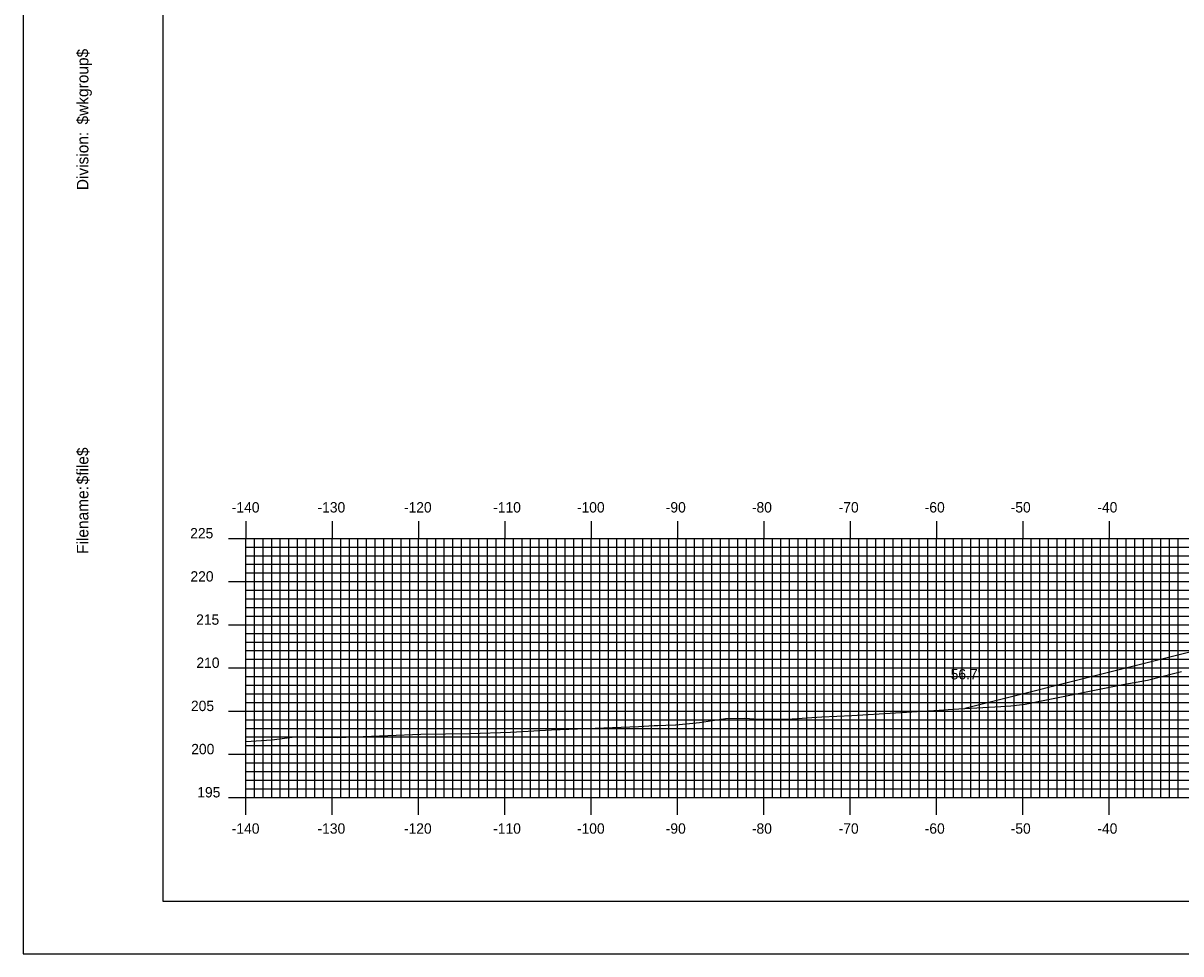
# Model space of a CAD drawing. Extents: x 852135 to 852479, y 364785 to 365005.
# Drawn here: x 852135.4 to 852269.5, y 364785.1 to 364892.9 of the extents above; entities that cross this region are included whole.
import ezdxf

# ---------------------------------------------------------------- set-up
doc = ezdxf.new("R2010")
doc.units = 0
for name, color, linetype in [('BORDER', 7, 'Continuous'), ('D_Roadway_SlopeLines', 7, 'Continuous'), ('D_Text_Standard', 7, 'Continuous'), ('H_V ANNOTATION', 7, 'Continuous'), ('MAJOR', 7, 'Continuous'), ('MINOR', 7, 'Continuous'), ('PLOT BOUNDARY', 7, 'Continuous'), ('S_Roadway_Centerline', 7, 'Continuous')]:
    doc.layers.add(name, color=color, linetype=linetype)

msp = doc.modelspace()

# ---------------------------------------------------------------- linework, layer by layer
at = {"layer": 'BORDER'}
msp.add_lwpolyline([(852151.62, 364791.23), (852471.62, 364791.23), (852471.62, 365001.23), (852151.62, 365001.23)], close=True, dxfattribs=at)
at = {"layer": 'D_Roadway_SlopeLines'}
msp.add_lwpolyline([(852281.22, 364822.7), (852244.53, 364813.53)], dxfattribs=at)
at = {"layer": 'MAJOR'}
for p, q in [((852161.22, 364835.24), (852161.22, 364833.23)), ((852171.22, 364835.24), (852171.22, 364833.23)), ((852181.22, 364835.24), (852181.22, 364833.23)), ((852191.22, 364835.24), (852191.22, 364833.23)), ((852201.22, 364835.24), (852201.22, 364833.23)), ((852211.22, 364835.24), (852211.22, 364833.23)), ((852221.22, 364835.24), (852221.22, 364833.23)), ((852231.22, 364835.24), (852231.22, 364833.23)), ((852241.22, 364835.24), (852241.22, 364833.23)), ((852251.22, 364835.24), (852251.22, 364833.23)), ((852261.22, 364835.24), (852261.22, 364833.23)), ((852159.21, 364833.23), (852161.22, 364833.23)), ((852161.22, 364833.23), (852441.22, 364833.23)), ((852161.22, 364803.23), (852161.22, 364833.23)), ((852161.22, 364803.23), (852161.22, 364833.23)), ((852161.22, 364833.23), (852441.22, 364833.23)), ((852171.22, 364803.23), (852171.22, 364833.23)), ((852181.22, 364803.23), (852181.22, 364833.23)), ((852191.22, 364803.23), (852191.22, 364833.23)), ((852201.22, 364803.23), (852201.22, 364833.23)), ((852211.22, 364803.23), (852211.22, 364833.23)), ((852221.22, 364803.23), (852221.22, 364833.23)), ((852231.22, 364803.23), (852231.22, 364833.23)), ((852241.22, 364803.23), (852241.22, 364833.23)), ((852251.22, 364803.23), (852251.22, 364833.23)), ((852261.22, 364803.23), (852261.22, 364833.23)), ((852159.21, 364828.23), (852161.22, 364828.23)), ((852161.22, 364828.23), (852441.22, 364828.23)), ((852159.21, 364823.23), (852161.22, 364823.23)), ((852161.22, 364823.23), (852441.22, 364823.23)), ((852159.21, 364818.23), (852161.22, 364818.23)), ((852161.22, 364818.23), (852441.22, 364818.23)), ((852159.21, 364813.23), (852161.22, 364813.23)), ((852161.22, 364813.23), (852441.22, 364813.23)), ((852159.21, 364808.23), (852161.22, 364808.23)), ((852161.22, 364808.23), (852441.22, 364808.23)), ((852159.21, 364803.23), (852161.22, 364803.23)), ((852161.22, 364803.23), (852441.22, 364803.23)), ((852161.22, 364803.23), (852441.22, 364803.23)), ((852161.22, 364801.23), (852161.22, 364803.23)), ((852171.22, 364801.23), (852171.22, 364803.23)), ((852181.22, 364801.23), (852181.22, 364803.23)), ((852191.22, 364801.23), (852191.22, 364803.23)), ((852201.22, 364801.23), (852201.22, 364803.23)), ((852211.22, 364801.23), (852211.22, 364803.23)), ((852221.22, 364801.23), (852221.22, 364803.23)), ((852231.22, 364801.23), (852231.22, 364803.23)), ((852241.22, 364801.23), (852241.22, 364803.23)), ((852251.22, 364801.23), (852251.22, 364803.23)), ((852261.22, 364801.23), (852261.22, 364803.23))]:
    msp.add_line(p, q, dxfattribs=at)
at = {"layer": 'MINOR'}
for p, q in [((852162.22, 364803.23), (852162.22, 364833.23)), ((852163.22, 364803.23), (852163.22, 364833.23)), ((852164.22, 364803.23), (852164.22, 364833.23)), ((852165.22, 364803.23), (852165.22, 364833.23)), ((852166.22, 364803.23), (852166.22, 364833.23)), ((852167.22, 364803.23), (852167.22, 364833.23)), ((852168.22, 364803.23), (852168.22, 364833.23)), ((852169.22, 364803.23), (852169.22, 364833.23)), ((852170.22, 364803.23), (852170.22, 364833.23)), ((852172.22, 364803.23), (852172.22, 364833.23)), ((852173.22, 364803.23), (852173.22, 364833.23)), ((852174.22, 364803.23), (852174.22, 364833.23)), ((852175.22, 364803.23), (852175.22, 364833.23)), ((852176.22, 364803.23), (852176.22, 364833.23)), ((852177.22, 364803.23), (852177.22, 364833.23)), ((852178.22, 364803.23), (852178.22, 364833.23)), ((852179.22, 364803.23), (852179.22, 364833.23)), ((852180.22, 364803.23), (852180.22, 364833.23)), ((852182.22, 364803.23), (852182.22, 364833.23)), ((852183.22, 364803.23), (852183.22, 364833.23)), ((852184.22, 364803.23), (852184.22, 364833.23)), ((852185.22, 364803.23), (852185.22, 364833.23)), ((852186.22, 364803.23), (852186.22, 364833.23)), ((852187.22, 364803.23), (852187.22, 364833.23)), ((852188.22, 364803.23), (852188.22, 364833.23)), ((852189.22, 364803.23), (852189.22, 364833.23)), ((852190.22, 364803.23), (852190.22, 364833.23)), ((852192.22, 364803.23), (852192.22, 364833.23)), ((852193.22, 364803.23), (852193.22, 364833.23)), ((852194.22, 364803.23), (852194.22, 364833.23)), ((852195.22, 364803.23), (852195.22, 364833.23)), ((852196.22, 364803.23), (852196.22, 364833.23)), ((852197.22, 364803.23), (852197.22, 364833.23)), ((852198.22, 364803.23), (852198.22, 364833.23)), ((852199.22, 364803.23), (852199.22, 364833.23)), ((852200.22, 364803.23), (852200.22, 364833.23)), ((852202.22, 364803.23), (852202.22, 364833.23)), ((852203.22, 364803.23), (852203.22, 364833.23)), ((852204.22, 364803.23), (852204.22, 364833.23)), ((852205.22, 364803.23), (852205.22, 364833.23)), ((852206.22, 364803.23), (852206.22, 364833.23)), ((852207.22, 364803.23), (852207.22, 364833.23)), ((852208.22, 364803.23), (852208.22, 364833.23)), ((852209.22, 364803.23), (852209.22, 364833.23)), ((852210.22, 364803.23), (852210.22, 364833.23)), ((852212.22, 364803.23), (852212.22, 364833.23)), ((852213.22, 364803.23), (852213.22, 364833.23)), ((852214.22, 364803.23), (852214.22, 364833.23)), ((852215.22, 364803.23), (852215.22, 364833.23)), ((852216.22, 364803.23), (852216.22, 364833.23)), ((852217.22, 364803.23), (852217.22, 364833.23)), ((852218.22, 364803.23), (852218.22, 364833.23)), ((852219.22, 364803.23), (852219.22, 364833.23)), ((852220.22, 364803.23), (852220.22, 364833.23)), ((852222.22, 364803.23), (852222.22, 364833.23)), ((852223.22, 364803.23), (852223.22, 364833.23)), ((852224.22, 364803.23), (852224.22, 364833.23)), ((852225.22, 364803.23), (852225.22, 364833.23)), ((852226.22, 364803.23), (852226.22, 364833.23)), ((852227.22, 364803.23), (852227.22, 364833.23)), ((852228.22, 364803.23), (852228.22, 364833.23)), ((852229.22, 364803.23), (852229.22, 364833.23)), ((852230.22, 364803.23), (852230.22, 364833.23)), ((852232.22, 364803.23), (852232.22, 364833.23)), ((852233.22, 364803.23), (852233.22, 364833.23)), ((852234.22, 364803.23), (852234.22, 364833.23)), ((852235.22, 364803.23), (852235.22, 364833.23)), ((852236.22, 364803.23), (852236.22, 364833.23)), ((852237.22, 364803.23), (852237.22, 364833.23)), ((852238.22, 364803.23), (852238.22, 364833.23)), ((852239.22, 364803.23), (852239.22, 364833.23)), ((852240.22, 364803.23), (852240.22, 364833.23)), ((852242.22, 364803.23), (852242.22, 364833.23)), ((852243.22, 364803.23), (852243.22, 364833.23)), ((852244.22, 364803.23), (852244.22, 364833.23)), ((852245.22, 364803.23), (852245.22, 364833.23)), ((852246.22, 364803.23), (852246.22, 364833.23)), ((852247.22, 364803.23), (852247.22, 364833.23)), ((852248.22, 364803.23), (852248.22, 364833.23)), ((852249.22, 364803.23), (852249.22, 364833.23)), ((852250.22, 364803.23), (852250.22, 364833.23)), ((852252.22, 364803.23), (852252.22, 364833.23)), ((852253.22, 364803.23), (852253.22, 364833.23)), ((852254.22, 364803.23), (852254.22, 364833.23)), ((852255.22, 364803.23), (852255.22, 364833.23)), ((852256.22, 364803.23), (852256.22, 364833.23)), ((852257.22, 364803.23), (852257.22, 364833.23)), ((852258.22, 364803.23), (852258.22, 364833.23)), ((852259.22, 364803.23), (852259.22, 364833.23)), ((852260.22, 364803.23), (852260.22, 364833.23)), ((852262.22, 364803.23), (852262.22, 364833.23)), ((852263.22, 364803.23), (852263.22, 364833.23)), ((852264.22, 364803.23), (852264.22, 364833.23)), ((852265.22, 364803.23), (852265.22, 364833.23)), ((852266.22, 364803.23), (852266.22, 364833.23)), ((852267.22, 364803.23), (852267.22, 364833.23)), ((852268.22, 364803.23), (852268.22, 364833.23)), ((852269.22, 364803.23), (852269.22, 364833.23)), ((852161.22, 364832.23), (852441.22, 364832.23)), ((852161.22, 364832.23), (852163.22, 364832.23)), ((852161.22, 364831.23), (852441.22, 364831.23)), ((852161.22, 364831.23), (852163.22, 364831.23)), ((852161.22, 364830.23), (852441.22, 364830.23)), ((852161.22, 364830.23), (852163.22, 364830.23)), ((852161.22, 364829.23), (852441.22, 364829.23)), ((852161.22, 364829.23), (852163.22, 364829.23)), ((852161.22, 364827.23), (852441.22, 364827.23)), ((852161.22, 364827.23), (852163.22, 364827.23)), ((852161.22, 364826.23), (852441.22, 364826.23)), ((852161.22, 364826.23), (852163.22, 364826.23)), ((852161.22, 364825.23), (852441.22, 364825.23)), ((852161.22, 364825.23), (852163.22, 364825.23)), ((852161.22, 364824.23), (852441.22, 364824.23)), ((852161.22, 364824.23), (852163.22, 364824.23)), ((852161.22, 364822.23), (852441.22, 364822.23)), ((852161.22, 364822.23), (852163.22, 364822.23)), ((852161.22, 364821.23), (852441.22, 364821.23)), ((852161.22, 364821.23), (852163.22, 364821.23)), ((852161.22, 364820.23), (852441.22, 364820.23)), ((852161.22, 364820.23), (852163.22, 364820.23)), ((852161.22, 364819.23), (852441.22, 364819.23)), ((852161.22, 364819.23), (852163.22, 364819.23)), ((852161.22, 364817.23), (852441.22, 364817.23)), ((852161.22, 364817.23), (852163.22, 364817.23)), ((852161.22, 364816.23), (852441.22, 364816.23)), ((852161.22, 364816.23), (852163.22, 364816.23)), ((852161.22, 364815.23), (852441.22, 364815.23)), ((852161.22, 364815.23), (852163.22, 364815.23)), ((852161.22, 364814.23), (852441.22, 364814.23)), ((852161.22, 364814.23), (852163.22, 364814.23)), ((852161.22, 364812.23), (852441.22, 364812.23)), ((852161.22, 364812.23), (852163.22, 364812.23)), ((852161.22, 364811.23), (852441.22, 364811.23)), ((852161.22, 364811.23), (852163.22, 364811.23)), ((852161.22, 364810.23), (852441.22, 364810.23)), ((852161.22, 364810.23), (852163.22, 364810.23)), ((852161.22, 364809.23), (852441.22, 364809.23)), ((852161.22, 364809.23), (852163.22, 364809.23)), ((852161.22, 364807.23), (852441.22, 364807.23)), ((852161.22, 364807.23), (852163.22, 364807.23)), ((852161.22, 364806.23), (852441.22, 364806.23)), ((852161.22, 364806.23), (852163.22, 364806.23)), ((852161.22, 364805.23), (852441.22, 364805.23)), ((852161.22, 364805.23), (852163.22, 364805.23)), ((852161.22, 364804.23), (852441.22, 364804.23)), ((852161.22, 364804.23), (852163.22, 364804.23))]:
    msp.add_line(p, q, dxfattribs=at)
at = {"layer": 'PLOT BOUNDARY'}
msp.add_lwpolyline([(852135.43, 364785.11), (852475.43, 364785.11), (852475.43, 365005.11), (852135.43, 365005.11)], close=True, dxfattribs=at)
at = {"layer": 'S_Roadway_Centerline'}
msp.add_lwpolyline([(852161.22, 364809.7), (852164.22, 364809.9), (852166.9, 364810.26), (852171.83, 364810.19), (852173.85, 364810.23), (852181.49, 364810.55), (852187.22, 364810.65), (852191.87, 364810.79), (852196.62, 364811.07), (852206.72, 364811.44), (852208.52, 364811.55), (852208.96, 364811.57), (852209.88, 364811.59), (852211.01, 364811.64), (852211.04, 364811.64), (852213.77, 364811.89), (852216.81, 364812.37), (852219.05, 364812.41), (852220.62, 364812.31), (852223.95, 364812.31), (852227.95, 364812.58), (852231.44, 364812.7), (852241.54, 364813.33), (852243.11, 364813.45), (852248.69, 364813.77), (852249.86, 364813.83), (852251.49, 364814.05), (852253.41, 364814.41), (852262.81, 364816.3), (852265.68, 364816.83), (852268.85, 364817.64), (852269.61, 364817.81)], dxfattribs=at)

# ---------------------------------------------------------------- texts
at = {"layer": 'BORDER'}
for s, p in [('$wkgroup$', (852142.99, 364881.17)), ('Division:', (852142.99, 364873.56)), ('$file$', (852142.99, 364839.48)), ('Filename:', (852142.99, 364831.43))]:
    msp.add_text(s, height=1.339, rotation=90, dxfattribs=at).set_placement(p)
at = {"layer": 'D_Text_Standard'}
msp.add_text("56.7'", height=1.2, dxfattribs=at).set_placement((852242.88, 364816.9))
at = {"layer": 'H_V ANNOTATION'}
for s, p in [('-140', (852159.6, 364836.23)), ('-130', (852169.53, 364836.23)), ('-120', (852179.54, 364836.23)), ('-110', (852189.88, 364836.23)), ('-100', (852199.58, 364836.23)), ('-90', (852209.87, 364836.23)), ('-80', (852219.85, 364836.23)), ('-70', (852229.9, 364836.23)), ('-60', (852239.87, 364836.23)), ('-50', (852249.83, 364836.23)), ('-40', (852259.87, 364836.23)), ('225', (852154.78, 364833.23)), ('220', (852154.81, 364828.23)), ('215', (852155.47, 364823.23)), ('210', (852155.5, 364818.23)), ('205', (852154.87, 364813.23)), ('200', (852154.9, 364808.23)), ('195', (852155.6, 364803.23)), ('-140', (852159.6, 364799.03)), ('-130', (852169.53, 364799.03)), ('-120', (852179.54, 364799.03)), ('-110', (852189.88, 364799.03)), ('-100', (852199.58, 364799.03)), ('-90', (852209.87, 364799.03)), ('-80', (852219.85, 364799.03)), ('-70', (852229.9, 364799.03)), ('-60', (852239.87, 364799.03)), ('-50', (852249.83, 364799.03)), ('-40', (852259.87, 364799.03))]:
    msp.add_text(s, height=1.2, dxfattribs=at).set_placement(p)
at = {"layer": 'MAJOR'}
msp.add_text('-', height=0.012, dxfattribs=at).set_placement((852161.21, 364803.23))

doc.saveas('drawing.dxf')
